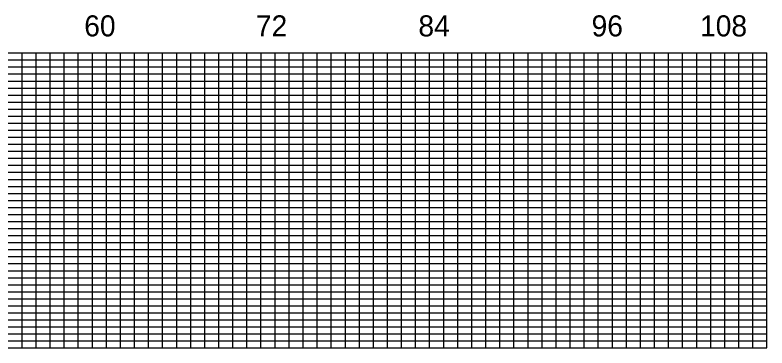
# Model space of a CAD drawing. Extents: x 1870112 to 1888282, y 758439 to 777406.
# Drawn here: x 1885607 to 1888282, y 775964 to 777149 of the extents above; entities that cross this region are included whole.
import ezdxf

# ---------------------------------------------------------------- set-up
doc = ezdxf.new("R2010")
doc.units = 0
doc.layers.add('RD_PD_WallFill', color=7, linetype='Continuous')

msp = doc.modelspace()

# ---------------------------------------------------------------- linework, layer by layer
at = {"layer": 'RD_PD_WallFill'}
for p, q in [((1882931.6, 777014.2), (1888281.6, 777014.2)), ((1885631.7, 775964.2), (1885631.6, 777014.2)), ((1885631.7, 775964.2), (1885631.6, 777014.2)), ((1885681.7, 775964.2), (1885681.6, 777014.2)), ((1885681.7, 775964.2), (1885681.6, 777014.2)), ((1885731.7, 775964.2), (1885731.6, 777014.2)), ((1885731.7, 775964.2), (1885731.6, 777014.2)), ((1885781.7, 775964.2), (1885781.6, 777014.2)), ((1885781.7, 775964.2), (1885781.6, 777014.2)), ((1885831.7, 775964.2), (1885831.6, 777014.2)), ((1885831.7, 775964.2), (1885831.6, 777014.2)), ((1885881.7, 775964.2), (1885881.7, 777014.2)), ((1885881.7, 775964.2), (1885881.7, 777014.2)), ((1885931.7, 775964.2), (1885931.7, 777014.2)), ((1885931.7, 775964.2), (1885931.7, 777014.2)), ((1885981.7, 775964.2), (1885981.7, 777014.2)), ((1885981.7, 775964.2), (1885981.7, 777014.2)), ((1886031.7, 775964.2), (1886031.7, 777014.2)), ((1886031.7, 775964.2), (1886031.7, 777014.2)), ((1886081.7, 775964.2), (1886081.7, 777014.2)), ((1886081.7, 775964.2), (1886081.7, 777014.2)), ((1886131.7, 775964.2), (1886131.7, 777014.2)), ((1886131.7, 775964.2), (1886131.7, 777014.2)), ((1886181.7, 775964.2), (1886181.7, 777014.2)), ((1886181.7, 775964.2), (1886181.7, 777014.2)), ((1886231.7, 775964.2), (1886231.7, 777014.2)), ((1886231.7, 775964.2), (1886231.7, 777014.2)), ((1886281.7, 775964.2), (1886281.7, 777014.2)), ((1886281.7, 775964.2), (1886281.7, 777014.2)), ((1886331.6, 775964.2), (1886331.7, 777014.2)), ((1886331.6, 775964.2), (1886331.7, 777014.2)), ((1886381.7, 775964.2), (1886381.7, 777014.2)), ((1886381.7, 775964.2), (1886381.7, 777014.2)), ((1886431.7, 775964.2), (1886431.7, 777014.2)), ((1886431.7, 775964.2), (1886431.7, 777014.2)), ((1886481.6, 775964.2), (1886481.7, 777014.2)), ((1886481.6, 775964.2), (1886481.7, 777014.2)), ((1886531.6, 775964.2), (1886531.7, 777014.2)), ((1886531.6, 775964.2), (1886531.7, 777014.2)), ((1886581.7, 775964.2), (1886581.7, 777014.2)), ((1886581.7, 775964.2), (1886581.7, 777014.2)), ((1886631.7, 775964.2), (1886631.7, 777014.2)), ((1886631.7, 775964.2), (1886631.7, 777014.2)), ((1886681.7, 775964.2), (1886681.7, 777014.2)), ((1886681.7, 775964.2), (1886681.7, 777014.2)), ((1886731.7, 775964.2), (1886731.7, 777014.2)), ((1886731.7, 775964.2), (1886731.7, 777014.2)), ((1886781.7, 775964.2), (1886781.7, 777014.2)), ((1886781.7, 775964.2), (1886781.7, 777014.2)), ((1886831.7, 775964.2), (1886831.7, 777014.2)), ((1886831.7, 775964.2), (1886831.7, 777014.2)), ((1886881.7, 775964.2), (1886881.7, 777014.2)), ((1886881.7, 775964.2), (1886881.7, 777014.2)), ((1886931.7, 775964.2), (1886931.7, 777014.2)), ((1886931.7, 775964.2), (1886931.7, 777014.2)), ((1886981.7, 775964.2), (1886981.7, 777014.2)), ((1886981.7, 775964.2), (1886981.7, 777014.2)), ((1887031.7, 775964.2), (1887031.7, 777014.2)), ((1887031.7, 775964.2), (1887031.7, 777014.2)), ((1887081.7, 775964.2), (1887081.7, 777014.2)), ((1887081.7, 775964.2), (1887081.7, 777014.2)), ((1887131.7, 775964.2), (1887131.7, 777014.2)), ((1887131.7, 775964.2), (1887131.7, 777014.2)), ((1887181.7, 775964.2), (1887181.7, 777014.2)), ((1887181.7, 775964.2), (1887181.7, 777014.2)), ((1887231.7, 775964.2), (1887231.7, 777014.2)), ((1887231.7, 775964.2), (1887231.7, 777014.2)), ((1887281.7, 775964.2), (1887281.7, 777014.2)), ((1887281.7, 775964.2), (1887281.7, 777014.2)), ((1887331.7, 775964.2), (1887331.7, 777014.2)), ((1887331.7, 775964.2), (1887331.7, 777014.2)), ((1887381.7, 775964.2), (1887381.7, 777014.2)), ((1887381.7, 775964.2), (1887381.7, 777014.2)), ((1887431.7, 775964.2), (1887431.7, 777014.2)), ((1887431.7, 775964.2), (1887431.7, 777014.2)), ((1887481.7, 775964.2), (1887481.7, 777014.2)), ((1887481.7, 775964.2), (1887481.7, 777014.2)), ((1887531.7, 775964.2), (1887531.7, 777014.2)), ((1887531.7, 775964.2), (1887531.7, 777014.2)), ((1887581.7, 775964.2), (1887581.7, 777014.2)), ((1887581.7, 775964.2), (1887581.7, 777014.2)), ((1887631.7, 775964.2), (1887631.7, 777014.2)), ((1887631.7, 775964.2), (1887631.7, 777014.2)), ((1887681.7, 775964.2), (1887681.7, 777014.2)), ((1887681.7, 775964.2), (1887681.7, 777014.2)), ((1887731.7, 775964.2), (1887731.7, 777014.2)), ((1887731.7, 775964.2), (1887731.7, 777014.2)), ((1887781.7, 775964.2), (1887781.7, 777014.2)), ((1887781.7, 775964.2), (1887781.7, 777014.2)), ((1887831.7, 775964.2), (1887831.7, 777014.2)), ((1887831.7, 775964.2), (1887831.7, 777014.2)), ((1887881.7, 775964.2), (1887881.7, 777014.2)), ((1887881.7, 775964.2), (1887881.7, 777014.2)), ((1887931.7, 775964.2), (1887931.7, 777014.2)), ((1887931.7, 775964.2), (1887931.7, 777014.2)), ((1887981.7, 775964.2), (1887981.7, 777014.2)), ((1887981.7, 775964.2), (1887981.7, 777014.2)), ((1888031.7, 775964.2), (1888031.7, 777014.2)), ((1888031.7, 775964.2), (1888031.7, 777014.2)), ((1888081.7, 775964.2), (1888081.7, 777014.2)), ((1888081.7, 775964.2), (1888081.7, 777014.2)), ((1888131.7, 775964.2), (1888131.7, 777014.2)), ((1888131.7, 775964.2), (1888131.7, 777014.2)), ((1888181.7, 775964.2), (1888181.7, 777014.2)), ((1888181.7, 775964.2), (1888181.7, 777014.2)), ((1888231.7, 775964.2), (1888231.7, 777014.2)), ((1888231.7, 775964.2), (1888231.7, 777014.2)), ((1888281.7, 775964.2), (1888281.7, 777014.2)), ((1888281.7, 775964.2), (1888281.7, 777014.2)), ((1883381.6, 776989.2), (1888281.6, 776989.2)), ((1883381.6, 776989.2), (1888281.6, 776989.2)), ((1883381.6, 776964.2), (1888281.6, 776964.2)), ((1883381.6, 776939.2), (1888281.6, 776939.2)), ((1883381.6, 776914.2), (1888281.6, 776914.2)), ((1883381.6, 776889.2), (1888281.6, 776889.2)), ((1882931.6, 776864.2), (1888281.6, 776864.2)), ((1882931.6, 776839.2), (1888281.6, 776839.2)), ((1882931.6, 776814.2), (1888281.6, 776814.2)), ((1882931.6, 776789.2), (1888281.6, 776789.2)), ((1882931.6, 776764.2), (1888281.6, 776764.2)), ((1882931.6, 776739.2), (1888281.6, 776739.2)), ((1882931.6, 776714.2), (1888281.6, 776714.2)), ((1882931.6, 776689.2), (1888281.6, 776689.2)), ((1882931.6, 776664.2), (1888281.6, 776664.2)), ((1882931.6, 776639.2), (1888281.6, 776639.2)), ((1882931.6, 776614.2), (1888281.6, 776614.2)), ((1882931.6, 776589.2), (1888281.6, 776589.2)), ((1882931.6, 776564.2), (1888281.6, 776564.2)), ((1882931.6, 776539.2), (1888281.6, 776539.2)), ((1882931.6, 776514.2), (1888281.6, 776514.2)), ((1882931.6, 776489.2), (1888281.6, 776489.2)), ((1882931.6, 776464.2), (1888281.6, 776464.2)), ((1882931.6, 776439.2), (1888281.6, 776439.2)), ((1882931.6, 776414.2), (1888281.6, 776414.2)), ((1882931.6, 776389.2), (1888281.6, 776389.2)), ((1882931.6, 776364.2), (1888281.6, 776364.2)), ((1882931.6, 776339.2), (1888281.6, 776339.2)), ((1882931.6, 776314.2), (1888281.6, 776314.2)), ((1882931.6, 776289.2), (1888281.6, 776289.2)), ((1882931.6, 776264.2), (1888281.6, 776264.2)), ((1882931.6, 776239.2), (1888281.6, 776239.2)), ((1882931.6, 776214.2), (1888281.6, 776214.2)), ((1882931.6, 776189.2), (1888281.6, 776189.2)), ((1882931.6, 776164.2), (1888281.6, 776164.2)), ((1882931.6, 776139.2), (1888281.6, 776139.2)), ((1882931.6, 776114.2), (1888281.6, 776114.2)), ((1882931.6, 776089.2), (1888281.6, 776089.2)), ((1882931.6, 776064.2), (1888281.6, 776064.2)), ((1882931.6, 776039.2), (1888281.6, 776039.2)), ((1882931.6, 776014.2), (1888281.6, 776014.2)), ((1882931.6, 775989.2), (1888281.6, 775989.2)), ((1882931.6, 775964.2), (1888281.6, 775964.2)), ((1882931.6, 775964.2), (1888281.6, 775964.2))]:
    msp.add_line(p, q, dxfattribs=at)

# ---------------------------------------------------------------- texts
for s, p in [('60', (1885852.8, 777072.9)), ('60', (1885852.8, 777072.9)), ('72', (1886463.5, 777072.9)), ('72', (1886463.5, 777072.9)), ('84', (1887041.7, 777072.9)), ('84', (1887041.7, 777072.9)), ('96', (1887657.8, 777072.9)), ('96', (1887657.8, 777072.9)), ('108', (1888043.6, 777072.9))]:
    msp.add_text(s, height=75, dxfattribs=at).set_placement(p)

doc.saveas('drawing.dxf')
